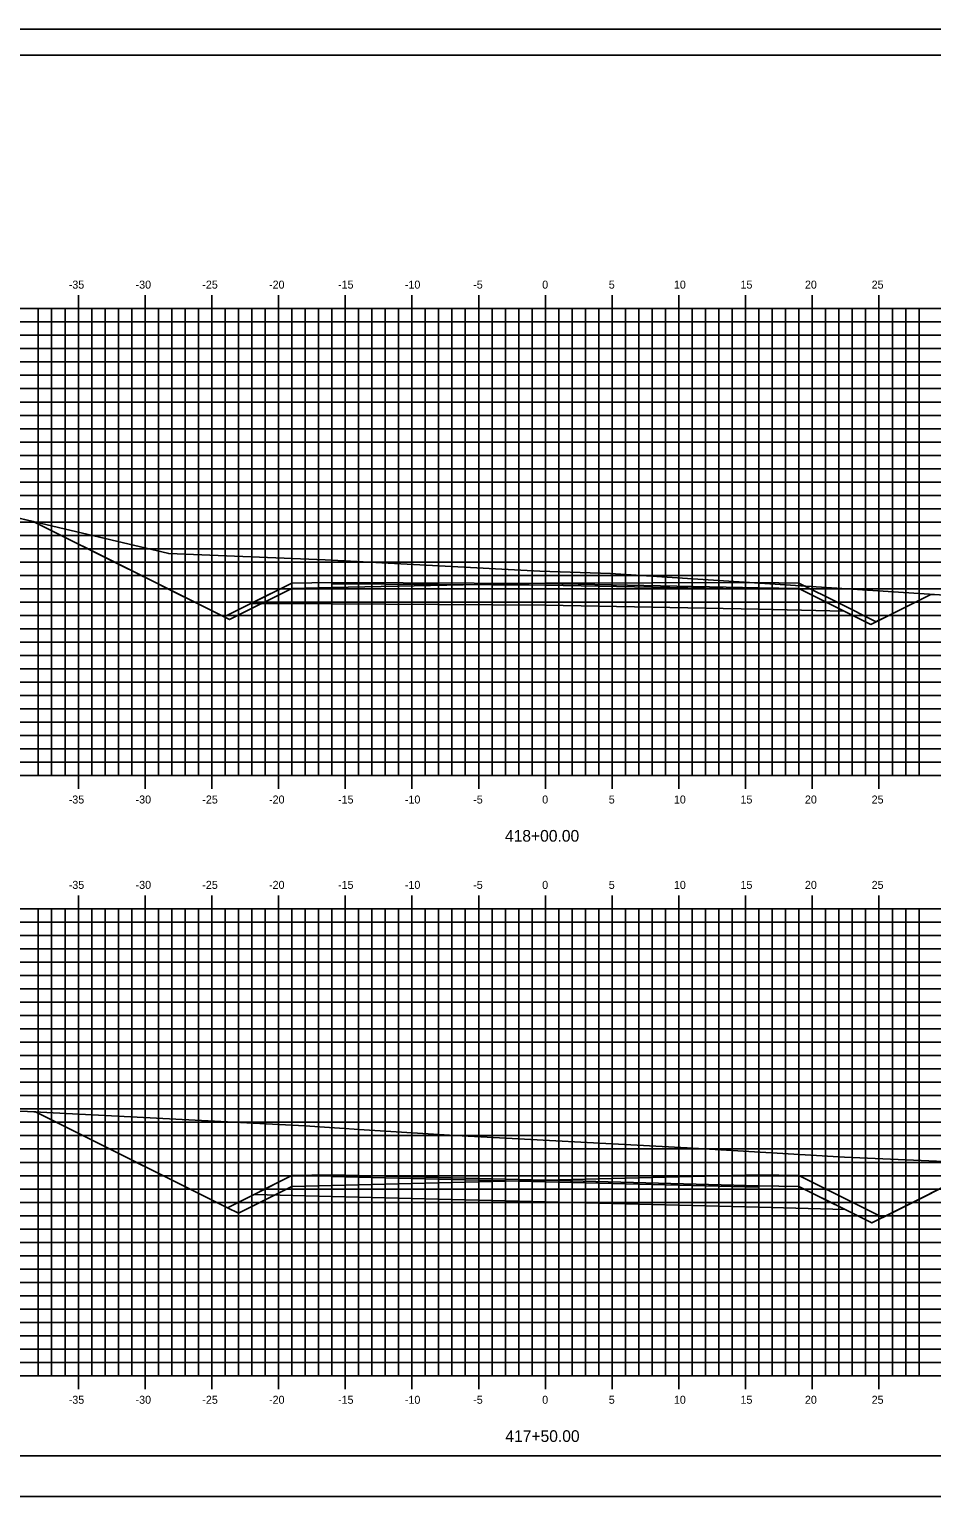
# Model space of a CAD drawing. Extents: x 1168600 to 1177589, y 610178 to 611246.
# Drawn here: x 1173372.7 to 1173440.3, y 610900.5 to 611010.5 of the extents above; entities that cross this region are included whole.
import ezdxf

# ---------------------------------------------------------------- set-up
doc = ezdxf.new("R2010")
doc.units = 0
for name, color, linetype in [('_Construction', 7, 'Continuous'), ('_Station Equation', 7, 'Continuous'), ('D_Roadway_Edge_TW', 7, 'Continuous'), ('D_Roadway_SubGrade', 7, 'Continuous'), ('D_Text_Standard', 7, 'Continuous'), ('DIMENSIONS', 7, 'Continuous'), ('H_V ANNOTATION', 7, 'Continuous'), ('MAJOR', 7, 'Continuous'), ('MATCH LINES', 7, 'Continuous'), ('MINOR', 7, 'Continuous')]:
    doc.layers.add(name, color=color, linetype=linetype)

msp = doc.modelspace()

# ---------------------------------------------------------------- linework, layer by layer
at = {"layer": '_Construction'}
for p, q in [((1173496.34, 611008.6), (1173336.34, 611008.6)), ((1173336.34, 610903.6), (1173496.34, 610903.6))]:
    msp.add_line(p, q, dxfattribs=at)
msp.add_lwpolyline([(1173328.25, 610900.54), (1173498.25, 610900.54), (1173498.25, 611010.54), (1173328.25, 611010.54)], close=True, dxfattribs=at)
at = {"layer": '_Station Equation'}
for points in [[(1173341.34, 610981.08), (1173383.12, 610971.24), (1173394.83, 610970.76), (1173410.92, 610969.92), (1173416.23, 610969.74), (1173440.5, 610968.17), (1173440.88, 610968.14), (1173444.19, 610967.89), (1173459.85, 610966.8), (1173460.53, 610966.54), (1173468.38, 610964.97), (1173474.2, 610967.49), (1173481.34, 610970.45)], [(1173341.34, 610981.08), (1173372.95, 610973.64), (1173373, 610973.62), (1173380.27, 610969.99), (1173381.2, 610969.52), (1173381.21, 610969.52), (1173383.84, 610968.2), (1173384.71, 610967.77), (1173387.22, 610966.51), (1173387.27, 610966.49), (1173387.27, 610966.49), (1173387.27, 610966.49), (1173387.27, 610966.49), (1173387.27, 610966.49), (1173387.27, 610966.49), (1173387.27, 610966.49), (1173387.67, 610966.29), (1173392.34, 610968.63), (1173392.34, 610968.63), (1173395.34, 610968.69), (1173411.34, 610969.01), (1173411.34, 610969.01), (1173411.34, 610969.01), (1173427.34, 610969.08), (1173427.34, 610969.08), (1173430.34, 610969.02), (1173433.41, 610967.49), (1173433.41, 610967.49), (1173436.12, 610966.13), (1173436.13, 610966.13), (1173436.13, 610966.13), (1173436.13, 610966.13), (1173436.18, 610966.16), (1173436.82, 610966.48), (1173438.82, 610967.48), (1173440.23, 610968.18), (1173440.28, 610968.18), (1173440.5, 610968.17)], [(1173341.34, 610935.31), (1173347.71, 610933.41), (1173356.24, 610930.83), (1173360.1, 610929.92), (1173372.54, 610929.41), (1173393.31, 610928.33), (1173397.76, 610928.04), (1173404.16, 610927.63), (1173421.96, 610926.68), (1173433.75, 610925.98), (1173441.81, 610925.65), (1173454.16, 610924.62), (1173458.8, 610924.46), (1173468.33, 610923.05), (1173470.95, 610922.77), (1173481.34, 610926.29)], [(1173372.54, 610929.41), (1173373.08, 610929.38), (1173373.13, 610929.38), (1173380.03, 610925.93), (1173381.2, 610925.35), (1173381.21, 610925.34), (1173384.28, 610923.81), (1173387.46, 610922.22), (1173387.48, 610922.21), (1173387.51, 610922.19), (1173387.51, 610922.19), (1173387.51, 610922.19), (1173388.34, 610921.78), (1173388.34, 610921.78), (1173392.34, 610923.78), (1173392.34, 610923.78), (1173395.34, 610923.86), (1173395.34, 610923.86), (1173411.34, 610924.26), (1173427.34, 610924.67), (1173427.34, 610924.67), (1173427.34, 610924.67), (1173430.34, 610924.61), (1173433.17, 610923.2), (1173433.17, 610923.2), (1173433.17, 610923.2), (1173436.62, 610921.47), (1173436.62, 610921.47), (1173436.67, 610921.5), (1173438.87, 610922.6), (1173441.74, 610924.03)]]:
    msp.add_lwpolyline(points, dxfattribs=at)
at = {"layer": 'D_Roadway_Edge_TW'}
for points in [[(1173395.34, 610968.96), (1173395.34, 610969.08), (1173411.34, 610969), (1173427.34, 610968.68), (1173427.34, 610968.56), (1173411.34, 610968.88)], [(1173395.34, 610924.55), (1173395.34, 610924.67), (1173411.34, 610924.26), (1173427.34, 610923.85), (1173427.34, 610923.73), (1173411.34, 610924.14)]]:
    msp.add_lwpolyline(points, close=True, dxfattribs=at)
at = {"layer": 'D_Roadway_SubGrade'}
for points in [[(1173395.34, 610969.08), (1173392.34, 610969.02), (1173389.27, 610967.49), (1173395.34, 610967.46)], [(1173395.34, 610967.46), (1173395.34, 610968.96), (1173411.34, 610968.88), (1173427.34, 610968.56), (1173427.34, 610967.06), (1173411.34, 610967.38)], [(1173427.34, 610968.68), (1173430.34, 610968.62), (1173433.73, 610966.93), (1173427.34, 610967.06)], [(1173395.34, 610924.67), (1173392.34, 610924.61), (1173389.51, 610923.19), (1173395.34, 610923.05)], [(1173395.34, 610923.05), (1173395.34, 610924.55), (1173411.34, 610924.14), (1173427.34, 610923.73), (1173427.34, 610922.23), (1173411.34, 610922.64)], [(1173427.34, 610923.85), (1173430.34, 610923.79), (1173433.8, 610922.06), (1173427.34, 610922.23)]]:
    msp.add_lwpolyline(points, close=True, dxfattribs=at)
at = {"layer": 'D_Text_Standard'}
for points in [[(1173373, 610973.62), (1173387.27, 610966.49), (1173392.34, 610969.02), (1173395.34, 610969.08), (1173411.34, 610969), (1173427.34, 610968.68), (1173430.34, 610968.62), (1173435.73, 610965.93), (1173440.23, 610968.18)], [(1173373.13, 610929.38), (1173387.51, 610922.19), (1173392.34, 610924.61), (1173395.34, 610924.67), (1173411.34, 610924.26), (1173427.34, 610923.85), (1173430.34, 610923.79), (1173435.8, 610921.06), (1173444.53, 610925.43)]]:
    msp.add_lwpolyline(points, dxfattribs=at)
at = {"layer": 'DIMENSIONS'}
for points in [[(1173395.34, 610968.96), (1173395.34, 610968.96), (1173411.34, 610968.88), (1173427.34, 610968.56), (1173427.34, 610968.56), (1173411.34, 610968.88)], [(1173395.34, 610924.55), (1173395.34, 610924.55), (1173411.34, 610924.14), (1173427.34, 610923.73), (1173427.34, 610923.73), (1173411.34, 610924.14)]]:
    msp.add_lwpolyline(points, close=True, dxfattribs=at)
for points in [[(1173395.34, 610968.96), (1173395.34, 610968.96)], [(1173395.34, 610968.96), (1173395.34, 610968.96)], [(1173427.34, 610968.56), (1173427.34, 610968.56)], [(1173427.34, 610968.56), (1173427.34, 610968.56)], [(1173395.34, 610924.55), (1173395.34, 610924.55)], [(1173395.34, 610924.55), (1173395.34, 610924.55)], [(1173427.34, 610923.73), (1173427.34, 610923.73)], [(1173427.34, 610923.73), (1173427.34, 610923.73)]]:
    msp.add_lwpolyline(points, dxfattribs=at)
at = {"layer": 'MAJOR'}
for p, q in [((1173341.34, 610989.6), (1173481.34, 610989.6)), ((1173341.34, 610989.6), (1173481.34, 610989.6)), ((1173376.34, 610990.6), (1173376.34, 610989.6)), ((1173376.34, 610954.6), (1173376.34, 610989.6)), ((1173381.34, 610990.6), (1173381.34, 610989.6)), ((1173381.34, 610954.6), (1173381.34, 610989.6)), ((1173386.34, 610990.6), (1173386.34, 610989.6)), ((1173386.34, 610954.6), (1173386.34, 610989.6)), ((1173391.34, 610990.6), (1173391.34, 610989.6)), ((1173391.34, 610954.6), (1173391.34, 610989.6)), ((1173396.34, 610990.6), (1173396.34, 610989.6)), ((1173396.34, 610954.6), (1173396.34, 610989.6)), ((1173401.34, 610990.6), (1173401.34, 610989.6)), ((1173401.34, 610954.6), (1173401.34, 610989.6)), ((1173406.34, 610990.6), (1173406.34, 610989.6)), ((1173406.34, 610954.6), (1173406.34, 610989.6)), ((1173411.34, 610990.6), (1173411.34, 610989.6)), ((1173411.34, 610954.6), (1173411.34, 610989.6)), ((1173416.34, 610990.6), (1173416.34, 610989.6)), ((1173416.34, 610954.6), (1173416.34, 610989.6)), ((1173421.34, 610990.6), (1173421.34, 610989.6)), ((1173421.34, 610954.6), (1173421.34, 610989.6)), ((1173426.34, 610990.6), (1173426.34, 610989.6)), ((1173426.34, 610954.6), (1173426.34, 610989.6)), ((1173431.34, 610990.6), (1173431.34, 610989.6)), ((1173431.34, 610954.6), (1173431.34, 610989.6)), ((1173436.34, 610990.6), (1173436.34, 610989.6)), ((1173436.34, 610954.6), (1173436.34, 610989.6)), ((1173341.34, 610984.6), (1173481.34, 610984.6)), ((1173341.34, 610979.6), (1173481.34, 610979.6)), ((1173341.34, 610974.6), (1173481.34, 610974.6)), ((1173341.34, 610969.6), (1173481.34, 610969.6)), ((1173341.34, 610964.6), (1173481.34, 610964.6)), ((1173341.34, 610959.6), (1173481.34, 610959.6)), ((1173341.34, 610954.6), (1173481.34, 610954.6)), ((1173341.34, 610954.6), (1173481.34, 610954.6)), ((1173376.34, 610953.59), (1173376.34, 610954.6)), ((1173381.34, 610953.59), (1173381.34, 610954.6)), ((1173386.34, 610953.59), (1173386.34, 610954.6)), ((1173391.34, 610953.59), (1173391.34, 610954.6)), ((1173396.34, 610953.59), (1173396.34, 610954.6)), ((1173401.34, 610953.59), (1173401.34, 610954.6)), ((1173406.34, 610953.59), (1173406.34, 610954.6)), ((1173411.34, 610953.59), (1173411.34, 610954.6)), ((1173416.34, 610953.59), (1173416.34, 610954.6)), ((1173421.34, 610953.59), (1173421.34, 610954.6)), ((1173426.34, 610953.59), (1173426.34, 610954.6)), ((1173431.34, 610953.59), (1173431.34, 610954.6)), ((1173436.34, 610953.59), (1173436.34, 610954.6)), ((1173376.34, 610945.6), (1173376.34, 610944.6)), ((1173381.34, 610945.6), (1173381.34, 610944.6)), ((1173386.34, 610945.6), (1173386.34, 610944.6)), ((1173391.34, 610945.6), (1173391.34, 610944.6)), ((1173396.34, 610945.6), (1173396.34, 610944.6)), ((1173401.34, 610945.6), (1173401.34, 610944.6)), ((1173406.34, 610945.6), (1173406.34, 610944.6)), ((1173411.34, 610945.6), (1173411.34, 610944.6)), ((1173416.34, 610945.6), (1173416.34, 610944.6)), ((1173421.34, 610945.6), (1173421.34, 610944.6)), ((1173426.34, 610945.6), (1173426.34, 610944.6)), ((1173431.34, 610945.6), (1173431.34, 610944.6)), ((1173436.34, 610945.6), (1173436.34, 610944.6)), ((1173341.34, 610944.6), (1173481.34, 610944.6)), ((1173341.34, 610944.6), (1173481.34, 610944.6)), ((1173376.34, 610909.6), (1173376.34, 610944.6)), ((1173381.34, 610909.6), (1173381.34, 610944.6)), ((1173386.34, 610909.6), (1173386.34, 610944.6)), ((1173391.34, 610909.6), (1173391.34, 610944.6)), ((1173396.34, 610909.6), (1173396.34, 610944.6)), ((1173401.34, 610909.6), (1173401.34, 610944.6)), ((1173406.34, 610909.6), (1173406.34, 610944.6)), ((1173411.34, 610909.6), (1173411.34, 610944.6)), ((1173416.34, 610909.6), (1173416.34, 610944.6)), ((1173421.34, 610909.6), (1173421.34, 610944.6)), ((1173426.34, 610909.6), (1173426.34, 610944.6)), ((1173431.34, 610909.6), (1173431.34, 610944.6)), ((1173436.34, 610909.6), (1173436.34, 610944.6)), ((1173341.34, 610939.6), (1173481.34, 610939.6)), ((1173341.34, 610934.6), (1173481.34, 610934.6)), ((1173341.34, 610929.6), (1173481.34, 610929.6)), ((1173341.34, 610924.6), (1173481.34, 610924.6)), ((1173341.34, 610919.6), (1173481.34, 610919.6)), ((1173341.34, 610914.6), (1173481.34, 610914.6)), ((1173341.34, 610909.6), (1173481.34, 610909.6)), ((1173341.34, 610909.6), (1173481.34, 610909.6)), ((1173376.34, 610908.59), (1173376.34, 610909.6)), ((1173381.34, 610908.59), (1173381.34, 610909.6)), ((1173386.34, 610908.59), (1173386.34, 610909.6)), ((1173391.34, 610908.59), (1173391.34, 610909.6)), ((1173396.34, 610908.59), (1173396.34, 610909.6)), ((1173401.34, 610908.59), (1173401.34, 610909.6)), ((1173406.34, 610908.59), (1173406.34, 610909.6)), ((1173411.34, 610908.59), (1173411.34, 610909.6)), ((1173416.34, 610908.59), (1173416.34, 610909.6)), ((1173421.34, 610908.59), (1173421.34, 610909.6)), ((1173426.34, 610908.59), (1173426.34, 610909.6)), ((1173431.34, 610908.59), (1173431.34, 610909.6)), ((1173436.34, 610908.59), (1173436.34, 610909.6))]:
    msp.add_line(p, q, dxfattribs=at)
at = {"layer": 'MATCH LINES'}
for points in [[(1173395.34, 610969.08), (1173395.34, 610968.96)], [(1173427.34, 610968.68), (1173427.34, 610968.56)], [(1173395.34, 610924.67), (1173395.34, 610924.55)], [(1173427.34, 610923.85), (1173427.34, 610923.73)]]:
    msp.add_lwpolyline(points, dxfattribs=at)
at = {"layer": 'MINOR'}
for p, q in [((1173373.34, 610954.6), (1173373.34, 610989.6)), ((1173374.34, 610954.6), (1173374.34, 610989.6)), ((1173375.34, 610954.6), (1173375.34, 610989.6)), ((1173377.34, 610954.6), (1173377.34, 610989.6)), ((1173378.34, 610954.6), (1173378.34, 610989.6)), ((1173379.34, 610954.6), (1173379.34, 610989.6)), ((1173380.34, 610954.6), (1173380.34, 610989.6)), ((1173382.34, 610954.6), (1173382.34, 610989.6)), ((1173383.34, 610954.6), (1173383.34, 610989.6)), ((1173384.34, 610954.6), (1173384.34, 610989.6)), ((1173385.34, 610954.6), (1173385.34, 610989.6)), ((1173387.34, 610954.6), (1173387.34, 610989.6)), ((1173388.34, 610954.6), (1173388.34, 610989.6)), ((1173389.34, 610954.6), (1173389.34, 610989.6)), ((1173390.34, 610954.6), (1173390.34, 610989.6)), ((1173392.34, 610954.6), (1173392.34, 610989.6)), ((1173393.34, 610954.6), (1173393.34, 610989.6)), ((1173394.34, 610954.6), (1173394.34, 610989.6)), ((1173395.34, 610954.6), (1173395.34, 610989.6)), ((1173397.34, 610954.6), (1173397.34, 610989.6)), ((1173398.34, 610954.6), (1173398.34, 610989.6)), ((1173399.34, 610954.6), (1173399.34, 610989.6)), ((1173400.34, 610954.6), (1173400.34, 610989.6)), ((1173402.34, 610954.6), (1173402.34, 610989.6)), ((1173403.34, 610954.6), (1173403.34, 610989.6)), ((1173404.34, 610954.6), (1173404.34, 610989.6)), ((1173405.34, 610954.6), (1173405.34, 610989.6)), ((1173407.34, 610954.6), (1173407.34, 610989.6)), ((1173408.34, 610954.6), (1173408.34, 610989.6)), ((1173409.34, 610954.6), (1173409.34, 610989.6)), ((1173410.34, 610954.6), (1173410.34, 610989.6)), ((1173412.34, 610954.6), (1173412.34, 610989.6)), ((1173413.34, 610954.6), (1173413.34, 610989.6)), ((1173414.34, 610954.6), (1173414.34, 610989.6)), ((1173415.34, 610954.6), (1173415.34, 610989.6)), ((1173417.34, 610954.6), (1173417.34, 610989.6)), ((1173418.34, 610954.6), (1173418.34, 610989.6)), ((1173419.34, 610954.6), (1173419.34, 610989.6)), ((1173420.34, 610954.6), (1173420.34, 610989.6)), ((1173422.34, 610954.6), (1173422.34, 610989.6)), ((1173423.34, 610954.6), (1173423.34, 610989.6)), ((1173424.34, 610954.6), (1173424.34, 610989.6)), ((1173425.34, 610954.6), (1173425.34, 610989.6)), ((1173427.34, 610954.6), (1173427.34, 610989.6)), ((1173428.34, 610954.6), (1173428.34, 610989.6)), ((1173429.34, 610954.6), (1173429.34, 610989.6)), ((1173430.34, 610954.6), (1173430.34, 610989.6)), ((1173432.34, 610954.6), (1173432.34, 610989.6)), ((1173433.34, 610954.6), (1173433.34, 610989.6)), ((1173434.34, 610954.6), (1173434.34, 610989.6)), ((1173435.34, 610954.6), (1173435.34, 610989.6)), ((1173437.34, 610954.6), (1173437.34, 610989.6)), ((1173438.34, 610954.6), (1173438.34, 610989.6)), ((1173439.34, 610954.6), (1173439.34, 610989.6)), ((1173341.34, 610988.6), (1173481.34, 610988.6)), ((1173341.34, 610987.6), (1173481.34, 610987.6)), ((1173341.34, 610986.6), (1173481.34, 610986.6)), ((1173341.34, 610985.6), (1173481.34, 610985.6)), ((1173341.34, 610983.6), (1173481.34, 610983.6)), ((1173341.34, 610982.6), (1173481.34, 610982.6)), ((1173341.34, 610981.6), (1173481.34, 610981.6)), ((1173341.34, 610980.6), (1173481.34, 610980.6)), ((1173341.34, 610978.6), (1173481.34, 610978.6)), ((1173341.34, 610977.6), (1173481.34, 610977.6)), ((1173341.34, 610976.6), (1173481.34, 610976.6)), ((1173341.34, 610975.6), (1173481.34, 610975.6)), ((1173341.34, 610973.6), (1173481.34, 610973.6)), ((1173341.34, 610972.6), (1173481.34, 610972.6)), ((1173341.34, 610971.6), (1173481.34, 610971.6)), ((1173341.34, 610970.6), (1173481.34, 610970.6)), ((1173341.34, 610968.6), (1173481.34, 610968.6)), ((1173341.34, 610967.6), (1173481.34, 610967.6)), ((1173341.34, 610966.6), (1173481.34, 610966.6)), ((1173341.34, 610965.6), (1173481.34, 610965.6)), ((1173341.34, 610963.6), (1173481.34, 610963.6)), ((1173341.34, 610962.6), (1173481.34, 610962.6)), ((1173341.34, 610961.6), (1173481.34, 610961.6)), ((1173341.34, 610960.6), (1173481.34, 610960.6)), ((1173341.34, 610958.6), (1173481.34, 610958.6)), ((1173341.34, 610957.6), (1173481.34, 610957.6)), ((1173341.34, 610956.6), (1173481.34, 610956.6)), ((1173341.34, 610955.6), (1173481.34, 610955.6)), ((1173373.34, 610909.6), (1173373.34, 610944.6)), ((1173374.34, 610909.6), (1173374.34, 610944.6)), ((1173375.34, 610909.6), (1173375.34, 610944.6)), ((1173377.34, 610909.6), (1173377.34, 610944.6)), ((1173378.34, 610909.6), (1173378.34, 610944.6)), ((1173379.34, 610909.6), (1173379.34, 610944.6)), ((1173380.34, 610909.6), (1173380.34, 610944.6)), ((1173382.34, 610909.6), (1173382.34, 610944.6)), ((1173383.34, 610909.6), (1173383.34, 610944.6)), ((1173384.34, 610909.6), (1173384.34, 610944.6)), ((1173385.34, 610909.6), (1173385.34, 610944.6)), ((1173387.34, 610909.6), (1173387.34, 610944.6)), ((1173388.34, 610909.6), (1173388.34, 610944.6)), ((1173389.34, 610909.6), (1173389.34, 610944.6)), ((1173390.34, 610909.6), (1173390.34, 610944.6)), ((1173392.34, 610909.6), (1173392.34, 610944.6)), ((1173393.34, 610909.6), (1173393.34, 610944.6)), ((1173394.34, 610909.6), (1173394.34, 610944.6)), ((1173395.34, 610909.6), (1173395.34, 610944.6)), ((1173397.34, 610909.6), (1173397.34, 610944.6)), ((1173398.34, 610909.6), (1173398.34, 610944.6)), ((1173399.34, 610909.6), (1173399.34, 610944.6)), ((1173400.34, 610909.6), (1173400.34, 610944.6)), ((1173402.34, 610909.6), (1173402.34, 610944.6)), ((1173403.34, 610909.6), (1173403.34, 610944.6)), ((1173404.34, 610909.6), (1173404.34, 610944.6)), ((1173405.34, 610909.6), (1173405.34, 610944.6)), ((1173407.34, 610909.6), (1173407.34, 610944.6)), ((1173408.34, 610909.6), (1173408.34, 610944.6)), ((1173409.34, 610909.6), (1173409.34, 610944.6)), ((1173410.34, 610909.6), (1173410.34, 610944.6)), ((1173412.34, 610909.6), (1173412.34, 610944.6)), ((1173413.34, 610909.6), (1173413.34, 610944.6)), ((1173414.34, 610909.6), (1173414.34, 610944.6)), ((1173415.34, 610909.6), (1173415.34, 610944.6)), ((1173417.34, 610909.6), (1173417.34, 610944.6)), ((1173418.34, 610909.6), (1173418.34, 610944.6)), ((1173419.34, 610909.6), (1173419.34, 610944.6)), ((1173420.34, 610909.6), (1173420.34, 610944.6)), ((1173422.34, 610909.6), (1173422.34, 610944.6)), ((1173423.34, 610909.6), (1173423.34, 610944.6)), ((1173424.34, 610909.6), (1173424.34, 610944.6)), ((1173425.34, 610909.6), (1173425.34, 610944.6)), ((1173427.34, 610909.6), (1173427.34, 610944.6)), ((1173428.34, 610909.6), (1173428.34, 610944.6)), ((1173429.34, 610909.6), (1173429.34, 610944.6)), ((1173430.34, 610909.6), (1173430.34, 610944.6)), ((1173432.34, 610909.6), (1173432.34, 610944.6)), ((1173433.34, 610909.6), (1173433.34, 610944.6)), ((1173434.34, 610909.6), (1173434.34, 610944.6)), ((1173435.34, 610909.6), (1173435.34, 610944.6)), ((1173437.34, 610909.6), (1173437.34, 610944.6)), ((1173438.34, 610909.6), (1173438.34, 610944.6)), ((1173439.34, 610909.6), (1173439.34, 610944.6)), ((1173341.34, 610943.6), (1173481.34, 610943.6)), ((1173341.34, 610942.6), (1173481.34, 610942.6)), ((1173341.34, 610941.6), (1173481.34, 610941.6)), ((1173341.34, 610940.6), (1173481.34, 610940.6)), ((1173341.34, 610938.6), (1173481.34, 610938.6)), ((1173341.34, 610937.6), (1173481.34, 610937.6)), ((1173341.34, 610936.6), (1173481.34, 610936.6)), ((1173341.34, 610935.6), (1173481.34, 610935.6)), ((1173341.34, 610933.6), (1173481.34, 610933.6)), ((1173341.34, 610932.6), (1173481.34, 610932.6)), ((1173341.34, 610931.6), (1173481.34, 610931.6)), ((1173341.34, 610930.6), (1173481.34, 610930.6)), ((1173341.34, 610928.6), (1173481.34, 610928.6)), ((1173341.34, 610927.6), (1173481.34, 610927.6)), ((1173341.34, 610926.6), (1173481.34, 610926.6)), ((1173341.34, 610925.6), (1173481.34, 610925.6)), ((1173341.34, 610923.6), (1173481.34, 610923.6)), ((1173341.34, 610922.6), (1173481.34, 610922.6)), ((1173341.34, 610921.6), (1173481.34, 610921.6)), ((1173341.34, 610920.6), (1173481.34, 610920.6)), ((1173341.34, 610918.6), (1173481.34, 610918.6)), ((1173341.34, 610917.6), (1173481.34, 610917.6)), ((1173341.34, 610916.6), (1173481.34, 610916.6)), ((1173341.34, 610915.6), (1173481.34, 610915.6)), ((1173341.34, 610913.6), (1173481.34, 610913.6)), ((1173341.34, 610912.6), (1173481.34, 610912.6)), ((1173341.34, 610911.6), (1173481.34, 610911.6)), ((1173341.34, 610910.6), (1173481.34, 610910.6))]:
    msp.add_line(p, q, dxfattribs=at)

# ---------------------------------------------------------------- texts
at = {"layer": 'H_V ANNOTATION'}
for s, height, p in [('-35', 0.6, (1173375.62, 610991.1)), ('-30', 0.6, (1173380.63, 610991.1)), ('-25', 0.6, (1173385.63, 610991.1)), ('-20', 0.6, (1173390.63, 610991.1)), ('-10', 0.6, (1173400.81, 610991.1)), ('0', 0.6, (1173411.1, 610991.1)), ('10', 0.6, (1173420.97, 610991.1)), ('20', 0.6, (1173430.79, 610991.1)), ('25', 0.6, (1173435.79, 610991.1)), ('-15', 0.6, (1173395.8, 610991.1)), ('-5', 0.6, (1173405.93, 610991.1)), ('5', 0.6, (1173416.09, 610991.1)), ('15', 0.6, (1173425.96, 610991.1)), ('-35', 0.6, (1173375.62, 610952.5)), ('-30', 0.6, (1173380.63, 610952.5)), ('-25', 0.6, (1173385.63, 610952.5)), ('-20', 0.6, (1173390.63, 610952.5)), ('-15', 0.6, (1173395.8, 610952.5)), ('-10', 0.6, (1173400.81, 610952.5)), ('-5', 0.6, (1173405.93, 610952.5)), ('0', 0.6, (1173411.1, 610952.5)), ('5', 0.6, (1173416.09, 610952.5)), ('10', 0.6, (1173420.97, 610952.5)), ('15', 0.6, (1173425.96, 610952.5)), ('20', 0.6, (1173430.79, 610952.5)), ('25', 0.6, (1173435.79, 610952.5)), ('418+00.00', 0.875, (1173408.31, 610949.64)), ('-35', 0.6, (1173375.62, 610946.1)), ('-30', 0.6, (1173380.63, 610946.1)), ('-25', 0.6, (1173385.63, 610946.1)), ('-20', 0.6, (1173390.63, 610946.1)), ('-15', 0.6, (1173395.8, 610946.1)), ('-10', 0.6, (1173400.81, 610946.1)), ('-5', 0.6, (1173405.93, 610946.1)), ('0', 0.6, (1173411.1, 610946.1)), ('5', 0.6, (1173416.09, 610946.1)), ('10', 0.6, (1173420.97, 610946.1)), ('15', 0.6, (1173425.96, 610946.1)), ('20', 0.6, (1173430.79, 610946.1)), ('25', 0.6, (1173435.79, 610946.1)), ('-35', 0.6, (1173375.62, 610907.5)), ('-30', 0.6, (1173380.63, 610907.5)), ('-25', 0.6, (1173385.63, 610907.5)), ('-20', 0.6, (1173390.63, 610907.5)), ('-10', 0.6, (1173400.81, 610907.5)), ('0', 0.6, (1173411.1, 610907.5)), ('10', 0.6, (1173420.97, 610907.5)), ('20', 0.6, (1173430.79, 610907.5)), ('25', 0.6, (1173435.79, 610907.5)), ('-15', 0.6, (1173395.8, 610907.5)), ('-5', 0.6, (1173405.93, 610907.5)), ('5', 0.6, (1173416.09, 610907.5)), ('15', 0.6, (1173425.96, 610907.5)), ('417+50.00', 0.875, (1173408.34, 610904.64))]:
    msp.add_text(s, height=height, dxfattribs=at).set_placement(p)

doc.saveas('drawing.dxf')
